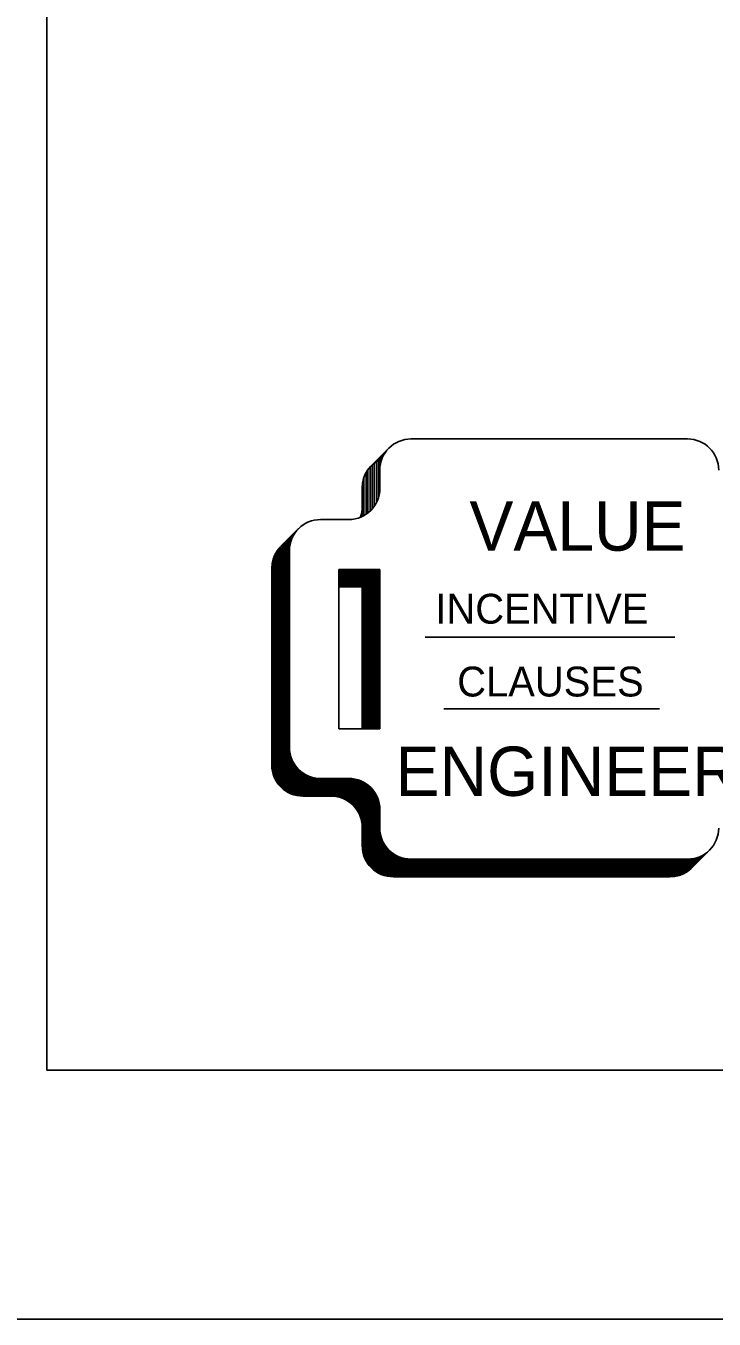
# Model space of a CAD drawing. Extents: x 4.9 to 31.6, y 3.9 to 22.6.
# Drawn here: x 5.879 to 6.8, y 3.926 to 5.658 of the extents above; entities that cross this region are included whole.
import ezdxf

# ---------------------------------------------------------------- set-up
doc = ezdxf.new("R2010")
doc.units = 0
doc.layers.add('Level 1', color=7, linetype='Continuous')

msp = doc.modelspace()

# ---------------------------------------------------------------- linework, layer by layer
at = {"layer": 'Level 1'}
for p, q in [((6.3414, 5.0687), (6.365, 5.0923)), ((6.7649, 5.1045), (6.3945, 5.1045)), ((6.3484, 5.0756), (6.3484, 5.0194)), ((6.3512, 5.0785), (6.3512, 5.0265)), ((6.3529, 5.0628), (6.3529, 5.0801)), ((6.3549, 5.0755), (6.3549, 5.0821)), ((6.357, 5.081), (6.357, 5.0843)), ((6.3591, 5.0847), (6.3591, 5.0864)), ((6.3609, 5.0874), (6.3609, 5.0881)), ((6.3344, 5.0591), (6.3344, 5.0035)), ((6.3369, 5.0633), (6.3369, 5.0055)), ((6.3398, 5.0669), (6.3398, 5.0079)), ((6.3425, 5.0698), (6.3425, 5.0107)), ((6.3454, 5.0726), (6.3454, 5.0144)), ((6.3529, 5.0628), (6.3529, 5.0382)), ((6.3293, 5.0392), (6.3293, 5.0007)), ((6.3315, 5.0527), (6.3315, 5.0019)), ((6.3112, 4.9965), (6.2735, 4.9965)), ((6.2204, 4.9608), (6.244, 4.9844)), ((6.2302, 4.9705), (6.2302, 4.6313)), ((6.2309, 4.9713), (6.2309, 4.6309)), ((6.2319, 4.9549), (6.2319, 4.9722)), ((6.2328, 4.9635), (6.2328, 4.9731)), ((6.2339, 4.9679), (6.2339, 4.9743)), ((6.2349, 4.9704), (6.2349, 4.9752)), ((6.2357, 4.9723), (6.2357, 4.976)), ((6.2364, 4.9739), (6.2364, 4.9768)), ((6.2373, 4.9755), (6.2373, 4.9776)), ((6.2381, 4.9768), (6.2381, 4.9785)), ((6.2389, 4.9781), (6.2389, 4.9793)), ((6.2398, 4.9793), (6.2398, 4.9801)), ((6.2144, 4.9531), (6.2144, 4.6461)), ((6.2158, 4.9551), (6.2158, 4.6441)), ((6.2172, 4.957), (6.2172, 4.6422)), ((6.2184, 4.9585), (6.2184, 4.6408)), ((6.2194, 4.9597), (6.2194, 4.6395)), ((6.2206, 4.9609), (6.2206, 4.6384)), ((6.222, 4.9624), (6.222, 4.637)), ((6.223, 4.9634), (6.223, 4.6361)), ((6.2241, 4.9645), (6.2241, 4.6353)), ((6.2254, 4.9658), (6.2254, 4.6343)), ((6.2269, 4.9672), (6.2269, 4.6333)), ((6.228, 4.9684), (6.228, 4.6325)), ((6.2291, 4.9695), (6.2291, 4.6319)), ((6.2319, 4.9549), (6.2319, 4.6915)), ((6.2094, 4.941), (6.2094, 4.6582)), ((6.2107, 4.9453), (6.2107, 4.654)), ((6.212, 4.9485), (6.212, 4.6507)), ((6.2131, 4.9508), (6.2131, 4.6485)), ((6.2083, 4.9313), (6.2083, 4.668)), ((6.3529, 4.9299), (6.2977, 4.9299)), ((6.2977, 4.7165), (6.2977, 4.9299)), ((6.3529, 4.9288), (6.2977, 4.9288)), ((6.3529, 4.9277), (6.2977, 4.9277)), ((6.3529, 4.9265), (6.2977, 4.9265)), ((6.3529, 4.9252), (6.2977, 4.9252)), ((6.3529, 4.9239), (6.2977, 4.9239)), ((6.3529, 4.9226), (6.2977, 4.9226)), ((6.3529, 4.9214), (6.2977, 4.9214)), ((6.3529, 4.92), (6.2977, 4.92)), ((6.3529, 4.9189), (6.2977, 4.9189)), ((6.3529, 4.9299), (6.3293, 4.9063)), ((6.3529, 4.7165), (6.3529, 4.9299)), ((6.3529, 4.9176), (6.2977, 4.9176)), ((6.3529, 4.9164), (6.2977, 4.9164)), ((6.3529, 4.9152), (6.2977, 4.9152)), ((6.3529, 4.914), (6.2977, 4.914)), ((6.3529, 4.913), (6.2977, 4.913)), ((6.3529, 4.9118), (6.2977, 4.9118)), ((6.3529, 4.9108), (6.2977, 4.9108)), ((6.3529, 4.9097), (6.2977, 4.9097)), ((6.3529, 4.9087), (6.2977, 4.9087)), ((6.3529, 4.9075), (6.2977, 4.9075)), ((6.3293, 4.9063), (6.2977, 4.9063)), ((6.3293, 4.7165), (6.3293, 4.9063)), ((6.3304, 4.7165), (6.3304, 4.9075)), ((6.3314, 4.7165), (6.3314, 4.9075)), ((6.3324, 4.7165), (6.3324, 4.9075)), ((6.3332, 4.7165), (6.3332, 4.9075)), ((6.3344, 4.7165), (6.3344, 4.9075)), ((6.3355, 4.7165), (6.3355, 4.9075)), ((6.3367, 4.7165), (6.3367, 4.9075)), ((6.3375, 4.7165), (6.3375, 4.9075)), ((6.3389, 4.7165), (6.3389, 4.9075)), ((6.3399, 4.7165), (6.3399, 4.9075)), ((6.3409, 4.7165), (6.3409, 4.9075)), ((6.3419, 4.7165), (6.3419, 4.9075)), ((6.343, 4.7165), (6.343, 4.9075)), ((6.3443, 4.7165), (6.3443, 4.9075)), ((6.3453, 4.7165), (6.3453, 4.9075)), ((6.3463, 4.7165), (6.3463, 4.9075)), ((6.3475, 4.7165), (6.3475, 4.9075)), ((6.3488, 4.7165), (6.3488, 4.9075)), ((6.35, 4.7165), (6.35, 4.9075)), ((6.3509, 4.7165), (6.3509, 4.9075)), ((6.3519, 4.7165), (6.3519, 4.9075)), ((6.4133, 4.8393), (6.7479, 4.8393)), ((6.4384, 4.7433), (6.7272, 4.7433)), ((6.3529, 4.7165), (6.2977, 4.7165)), ((6.2324, 4.6846), (6.2324, 4.6301)), ((6.2338, 4.679), (6.2338, 4.6295)), ((6.235, 4.6756), (6.235, 4.629)), ((6.2363, 4.6729), (6.2363, 4.6286)), ((6.2378, 4.6701), (6.2378, 4.6281)), ((6.2389, 4.6685), (6.2389, 4.6278)), ((6.2399, 4.6669), (6.2399, 4.6275)), ((6.2414, 4.665), (6.2414, 4.6272)), ((6.2425, 4.6637), (6.2425, 4.627)), ((6.2438, 4.6624), (6.2438, 4.6268)), ((6.245, 4.6611), (6.245, 4.6265)), ((6.2463, 4.66), (6.2463, 4.6265)), ((6.2474, 4.659), (6.2474, 4.6264)), ((6.2489, 4.658), (6.2489, 4.6263)), ((6.2501, 4.657), (6.2501, 4.6263)), ((6.2514, 4.6563), (6.2514, 4.6263)), ((6.2526, 4.6555), (6.2526, 4.6263)), ((6.2541, 4.6547), (6.2541, 4.6263)), ((6.2552, 4.6541), (6.2552, 4.6263)), ((6.2559, 4.6538), (6.2559, 4.6263)), ((6.2569, 4.6533), (6.2569, 4.6263)), ((6.258, 4.6529), (6.258, 4.6263)), ((6.2594, 4.6524), (6.2594, 4.6263)), ((6.2607, 4.6519), (6.2607, 4.6263)), ((6.2619, 4.6515), (6.2619, 4.6263)), ((6.2636, 4.651), (6.2636, 4.6263)), ((6.2651, 4.6507), (6.2651, 4.6263)), ((6.2664, 4.6505), (6.2664, 4.6263)), ((6.2673, 4.6504), (6.2673, 4.6263)), ((6.2685, 4.6502), (6.2685, 4.6263)), ((6.2696, 4.65), (6.2696, 4.6263)), ((6.2705, 4.65), (6.2705, 4.6263)), ((6.2717, 4.6499), (6.2717, 4.6263)), ((6.273, 4.6499), (6.273, 4.6263)), ((6.2735, 4.6499), (6.3112, 4.6499)), ((6.2743, 4.6499), (6.2743, 4.6263)), ((6.2757, 4.6499), (6.2757, 4.6263)), ((6.2771, 4.6499), (6.2771, 4.6263)), ((6.2784, 4.6499), (6.2784, 4.6263)), ((6.28, 4.6499), (6.28, 4.6263)), ((6.2814, 4.6499), (6.2814, 4.6263)), ((6.2827, 4.6499), (6.2827, 4.6263)), ((6.2841, 4.6499), (6.2841, 4.6263)), ((6.2857, 4.6499), (6.2857, 4.6263)), ((6.2872, 4.6499), (6.2872, 4.6263)), ((6.2888, 4.6499), (6.2888, 4.6263)), ((6.2904, 4.6499), (6.2904, 4.6263)), ((6.2922, 4.6499), (6.2922, 4.626)), ((6.2934, 4.6499), (6.2934, 4.6259)), ((6.2945, 4.6499), (6.2945, 4.6257)), ((6.2956, 4.6499), (6.2956, 4.6255)), ((6.2974, 4.6499), (6.2974, 4.6251)), ((6.2992, 4.6499), (6.2992, 4.6246)), ((6.3011, 4.6499), (6.3011, 4.624)), ((6.3029, 4.6499), (6.3029, 4.6234)), ((6.3045, 4.6499), (6.3045, 4.6227)), ((6.3064, 4.6499), (6.3064, 4.6219)), ((6.3078, 4.6499), (6.3078, 4.6211)), ((6.3099, 4.6499), (6.3099, 4.6198)), ((6.3117, 4.6499), (6.3117, 4.6186)), ((6.3126, 4.6499), (6.3126, 4.618)), ((6.3142, 4.6499), (6.3142, 4.6167)), ((6.3154, 4.6496), (6.3154, 4.6156)), ((6.3168, 4.6495), (6.3168, 4.6144)), ((6.318, 4.6493), (6.318, 4.6131)), ((6.3189, 4.6491), (6.3189, 4.6121)), ((6.3204, 4.6489), (6.3204, 4.6104)), ((6.3218, 4.6485), (6.3218, 4.6085)), ((6.3233, 4.6481), (6.3233, 4.6061)), ((6.3247, 4.6476), (6.3247, 4.6036)), ((6.3259, 4.6472), (6.3259, 4.601)), ((6.3273, 4.6466), (6.3273, 4.5974)), ((6.3287, 4.646), (6.3287, 4.5915)), ((6.3298, 4.6455), (6.3298, 4.5536)), ((6.3311, 4.6448), (6.3311, 4.5478)), ((6.3324, 4.644), (6.3324, 4.5441)), ((6.3337, 4.6433), (6.3337, 4.5414)), ((6.3349, 4.6425), (6.3349, 4.539)), ((6.3362, 4.6415), (6.3362, 4.537)), ((6.2499, 4.6263), (6.2876, 4.6263)), ((6.3376, 4.6405), (6.3376, 4.535)), ((6.3387, 4.6395), (6.3387, 4.5336)), ((6.3399, 4.6384), (6.3399, 4.5322)), ((6.341, 4.6373), (6.341, 4.531)), ((6.3424, 4.6359), (6.3424, 4.5297)), ((6.3436, 4.6344), (6.3436, 4.5286)), ((6.345, 4.6325), (6.345, 4.5274)), ((6.3464, 4.6305), (6.3464, 4.5264)), ((6.3474, 4.6288), (6.3474, 4.5256)), ((6.3484, 4.6269), (6.3484, 4.525)), ((6.3493, 4.6251), (6.3493, 4.5245)), ((6.3504, 4.6225), (6.3504, 4.5238)), ((6.3513, 4.6196), (6.3513, 4.5233)), ((6.352, 4.6165), (6.352, 4.5229)), ((6.3529, 4.6082), (6.3529, 4.5836)), ((6.3293, 4.5846), (6.3293, 4.56)), ((6.3529, 4.581), (6.3529, 4.5225)), ((6.3541, 4.5735), (6.3541, 4.522)), ((6.3552, 4.5699), (6.3552, 4.5215)), ((6.3561, 4.5675), (6.3561, 4.5211)), ((6.3571, 4.5653), (6.3571, 4.5207)), ((6.3579, 4.5637), (6.3579, 4.5205)), ((6.3591, 4.5617), (6.3591, 4.5201)), ((6.3602, 4.56), (6.3602, 4.5198)), ((6.3614, 4.5584), (6.3614, 4.5195)), ((6.3622, 4.5574), (6.3622, 4.5193)), ((6.3634, 4.556), (6.3634, 4.519)), ((6.364, 4.5552), (6.364, 4.519)), ((6.3649, 4.5543), (6.3649, 4.5188)), ((6.7708, 4.5305), (6.7944, 4.5541)), ((6.3659, 4.5533), (6.3659, 4.5187)), ((6.3667, 4.5526), (6.3667, 4.5186)), ((6.3672, 4.5522), (6.3672, 4.5185)), ((6.3678, 4.5517), (6.3678, 4.5185)), ((6.3687, 4.551), (6.3687, 4.5185)), ((6.3699, 4.55), (6.3699, 4.5185)), ((6.3712, 4.5491), (6.3712, 4.5185)), ((6.3724, 4.5484), (6.3724, 4.5185)), ((6.3737, 4.5475), (6.3737, 4.5185)), ((6.3749, 4.5469), (6.3749, 4.5185)), ((6.3762, 4.5462), (6.3762, 4.5185)), ((6.3772, 4.5457), (6.3772, 4.5185)), ((6.3784, 4.5452), (6.3784, 4.5185)), ((6.3797, 4.5447), (6.3797, 4.5185)), ((6.381, 4.5442), (6.381, 4.5185)), ((6.3824, 4.5438), (6.3824, 4.5185)), ((6.3838, 4.5434), (6.3838, 4.5185)), ((6.3853, 4.543), (6.3853, 4.5185)), ((6.3864, 4.5427), (6.3864, 4.5185)), ((6.3879, 4.5425), (6.3879, 4.5185)), ((6.3893, 4.5423), (6.3893, 4.5185)), ((6.3906, 4.5421), (6.3906, 4.5185)), ((6.3922, 4.542), (6.3922, 4.5185)), ((6.3935, 4.542), (6.3935, 4.5185)), ((6.3935, 4.5414), (6.7413, 4.5414)), ((6.3935, 4.541), (6.7413, 4.541)), ((6.3935, 4.5405), (6.7413, 4.5405)), ((6.3935, 4.54), (6.7413, 4.54)), ((6.3935, 4.5393), (6.7413, 4.5393)), ((6.3935, 4.5385), (6.7413, 4.5385)), ((6.3935, 4.5378), (6.7413, 4.5378)), ((6.3935, 4.5371), (6.7413, 4.5371)), ((6.3945, 4.542), (6.7649, 4.542)), ((6.7413, 4.5184), (6.7413, 4.542)), ((6.7422, 4.5184), (6.7422, 4.542)), ((6.7429, 4.5184), (6.7429, 4.542)), ((6.7435, 4.5185), (6.7435, 4.542)), ((6.7446, 4.5185), (6.7446, 4.542)), ((6.7454, 4.5186), (6.7454, 4.542)), ((6.7464, 4.5187), (6.7464, 4.542)), ((6.7473, 4.5188), (6.7473, 4.542)), ((6.7482, 4.519), (6.7482, 4.542)), ((6.7489, 4.5191), (6.7489, 4.542)), ((6.7499, 4.5193), (6.7499, 4.542)), ((6.7509, 4.5195), (6.7509, 4.542)), ((6.7518, 4.5197), (6.7518, 4.542)), ((6.7529, 4.52), (6.7529, 4.542)), ((6.7542, 4.5205), (6.7542, 4.542)), ((6.7552, 4.5208), (6.7552, 4.542)), ((6.7562, 4.5211), (6.7562, 4.542)), ((6.7573, 4.5215), (6.7573, 4.542)), ((6.7584, 4.522), (6.7584, 4.542)), ((6.7593, 4.5225), (6.7593, 4.542)), ((6.7605, 4.5231), (6.7605, 4.542)), ((6.7618, 4.5238), (6.7618, 4.542)), ((6.7629, 4.5245), (6.7629, 4.542)), ((6.7641, 4.5252), (6.7641, 4.542)), ((6.7653, 4.526), (6.7653, 4.542)), ((6.7664, 4.5268), (6.7664, 4.542)), ((6.7675, 4.5277), (6.7675, 4.542)), ((6.7688, 4.5287), (6.7688, 4.5421)), ((6.7699, 4.5298), (6.7699, 4.5423)), ((6.7709, 4.5307), (6.7709, 4.5424)), ((6.772, 4.5318), (6.772, 4.5425)), ((6.7729, 4.5326), (6.7729, 4.5427)), ((6.7739, 4.5336), (6.7739, 4.543)), ((6.7747, 4.5345), (6.7747, 4.5431)), ((6.7756, 4.5354), (6.7756, 4.5434)), ((6.7766, 4.5364), (6.7766, 4.5436)), ((6.7773, 4.537), (6.7773, 4.5439)), ((6.7781, 4.5379), (6.7781, 4.5441)), ((6.7789, 4.5386), (6.7789, 4.5444)), ((6.7797, 4.5395), (6.7797, 4.5447)), ((6.7802, 4.54), (6.7802, 4.5449)), ((6.7812, 4.541), (6.7812, 4.5453)), ((6.7819, 4.5417), (6.7819, 4.5456)), ((6.7828, 4.5425), (6.7828, 4.546)), ((6.7837, 4.5435), (6.7837, 4.5465)), ((6.7844, 4.5442), (6.7844, 4.5469)), ((6.7852, 4.545), (6.7852, 4.5473)), ((6.7859, 4.5457), (6.7859, 4.5477)), ((6.7868, 4.5465), (6.7868, 4.5482)), ((6.7876, 4.5474), (6.7876, 4.5487)), ((6.7884, 4.5481), (6.7884, 4.5492)), ((6.7891, 4.5489), (6.7891, 4.5497)), ((6.7899, 4.5496), (6.7899, 4.5503)), ((6.3935, 4.5364), (6.7413, 4.5364)), ((6.3935, 4.5356), (6.7413, 4.5356)), ((6.3935, 4.5349), (6.7413, 4.5349)), ((6.3935, 4.5341), (6.7413, 4.5341)), ((6.3935, 4.5334), (6.7413, 4.5334)), ((6.3935, 4.5327), (6.7413, 4.5327)), ((6.3935, 4.532), (6.7413, 4.532)), ((6.3935, 4.5313), (6.7413, 4.5313)), ((6.3935, 4.5306), (6.7413, 4.5306)), ((6.3935, 4.5299), (6.7413, 4.5299)), ((6.3935, 4.5291), (6.7413, 4.5291)), ((6.3935, 4.5283), (6.7413, 4.5283)), ((6.3935, 4.5275), (6.7413, 4.5275)), ((6.3935, 4.5266), (6.7413, 4.5266)), ((6.3935, 4.5259), (6.7413, 4.5259)), ((6.3935, 4.525), (6.7413, 4.525)), ((6.3935, 4.5241), (6.7413, 4.5241)), ((6.3935, 4.5232), (6.7413, 4.5232)), ((6.3935, 4.5223), (6.7413, 4.5223)), ((6.3935, 4.5213), (6.7413, 4.5213)), ((6.3935, 4.5204), (6.7413, 4.5204)), ((6.3935, 4.5195), (6.7413, 4.5195)), ((6.3709, 4.5184), (6.7413, 4.5184))]:
    msp.add_line(p, q, dxfattribs=at)
for points in [[(4.9069, 22.5927), (31.5735, 22.5927), (31.5735, 3.926), (4.9069, 3.926)], [(5.9069, 22.2594), (31.2402, 22.2594), (31.2402, 4.2594), (5.9069, 4.2594)]]:
    msp.add_lwpolyline(points, close=True, dxfattribs=at)
for centre, start, end in [((6.3945, 5.0628), 90, 180), ((6.7649, 5.0628), 0, 90), ((6.3709, 5.0392), 111.4079, 180), ((6.3112, 5.0382), 270, 0), ((6.2876, 5.0146), 338.5921, 0), ((6.2735, 4.9549), 90, 180), ((6.2499, 4.9313), 111.4079, 180), ((6.2735, 4.6915), 180, 270), ((6.2499, 4.668), 180, 270), ((6.3112, 4.6082), 0, 90), ((6.2876, 4.5846), 0, 90), ((6.3945, 4.5836), 180, 270), ((6.7649, 4.5836), 270, 0), ((6.3709, 4.56), 180, 270), ((6.7413, 4.56), 270, 338.5921)]:
    msp.add_arc(centre, 0.0417, start, end, dxfattribs=at)

# ---------------------------------------------------------------- texts
for s, height, p in [('VALUE', 0.066, (6.4728, 4.9549)), ('INCENTIVE', 0.04, (6.4271, 4.8572)), ('CLAUSES', 0.04, (6.4564, 4.7597)), ('ENGINEERING', 0.065995, (6.3739, 4.6266))]:
    msp.add_text(s, height=height, dxfattribs=at).set_placement(p)

doc.saveas('drawing.dxf')
